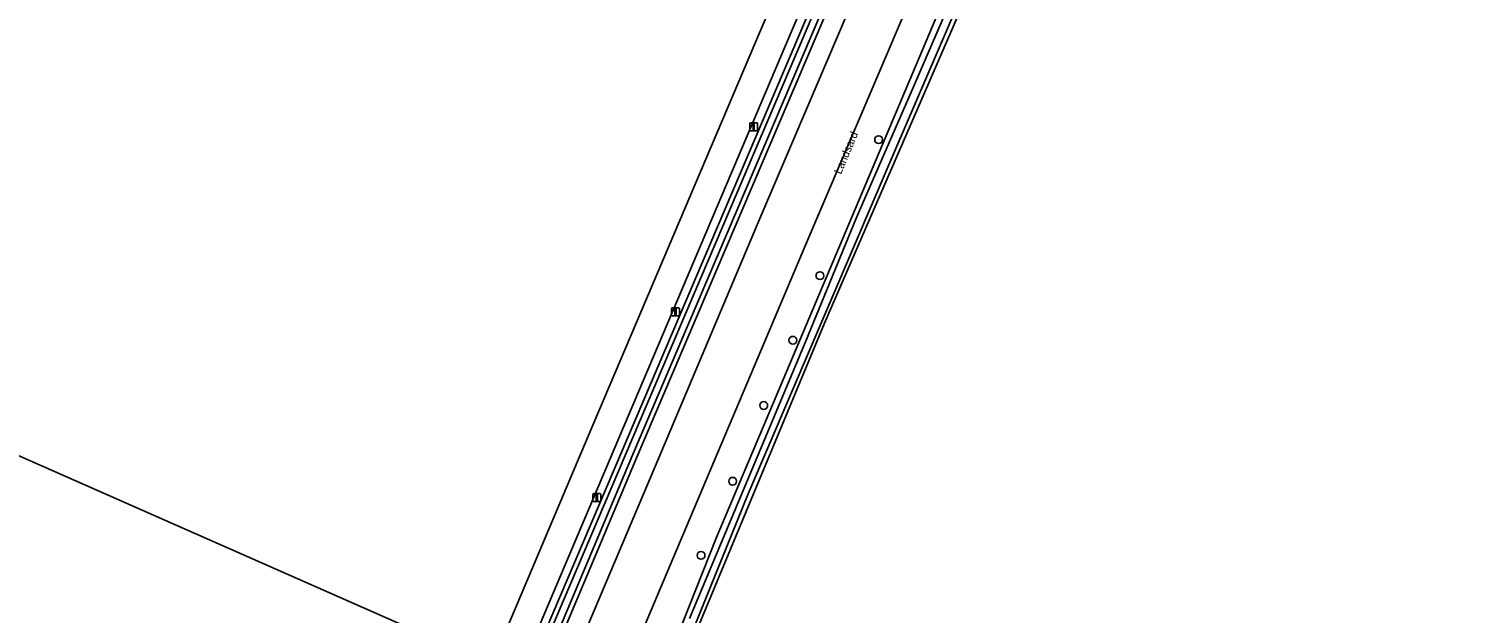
# Model space of a CAD drawing. Extents: x 155209 to 156748, y 385356 to 388487.
# Drawn here: x 155996.7 to 156175.3, y 386329.7 to 386402.7 of the extents above; entities that cross this region are included whole.
import ezdxf

# ---------------------------------------------------------------- set-up
doc = ezdxf.new("R2010")
doc.units = 0
for name, color, linetype in [('IMGEO_Boom', 7, 'Continuous'), ('IMGEO_Bouwland', 7, 'Continuous'), ('IMGEO_Fietspad_gesloten', 7, 'Continuous'), ('IMGEO_Gemengd_bos', 7, 'Continuous'), ('IMGEO_Groenvoorziening', 7, 'Continuous'), ('IMGEO_Lichtmast', 7, 'Continuous'), ('IMGEO_Oever', 7, 'Continuous'), ('IMGEO_Openbare_ruimte_label', 7, 'Continuous'), ('IMGEO_Rijbaan_lokaal_gesloten', 7, 'Continuous'), ('IMGEO_Waterloop', 7, 'Continuous')]:
    doc.layers.add(name, color=color, linetype=linetype)

msp = doc.modelspace()

# ---------------------------------------------------------------- linework, layer by layer
at = {"layer": 'IMGEO_Boom'}
for centre in [(156102.88, 386388.85), (156095.55, 386371.87), (156092.17, 386363.81), (156088.53, 386355.67), (156084.64, 386346.21), (156080.7, 386336.96)]:
    msp.add_circle(centre, 0.489, dxfattribs=at)
at = {"layer": 'IMGEO_Bouwland'}
msp.add_lwpolyline([(156111.26, 386456.76), (156125.52, 386490.13), (155948.54, 386558.13), (155923.76, 386500), (155881.05, 386399.78), (156052.24, 386324.4), (156054.54, 386323.39), (156054.72, 386323.81), (156066.59, 386351.85), (156087.98, 386402.17)], close=True, dxfattribs=at)
at = {"layer": 'IMGEO_Fietspad_gesloten'}
for points in [[(156139.32, 386522.4), (156125.52, 386490.13), (156111.26, 386456.76), (156087.98, 386402.17), (156066.59, 386351.85), (156054.72, 386323.81), (156054.54, 386323.39), (156042.98, 386296.08), (156023.43, 386249.93), (156022.29, 386247.24), (156019.64, 386240.99), (156006.63, 386210.28), (156004.07, 386204.24), (156001.82, 386199.14)], [(156005, 386197.04), (156010, 386208.82), (156023.01, 386239.56), (156046.41, 386294.89), (156058.06, 386322.41), (156069.84, 386350.23), (156091.23, 386400.62), (156114.61, 386455.4), (156142.59, 386521.01)]]:
    msp.add_lwpolyline(points, dxfattribs=at)
at = {"layer": 'IMGEO_Gemengd_bos'}
msp.add_lwpolyline([(156141.39, 386470.18), (156096.12, 386365.96), (156080.46, 386328.34), (156070.14, 386302.11), (156116.28, 386284.55), (156115.74, 386281.76), (156114.94, 386278.94), (156085.5, 386176.9)], dxfattribs=at)
msp.add_lwpolyline([(156052.24, 386324.4), (155881.05, 386399.78), (155850.31, 386327.79), (155900.27, 386304.88), (156000, 386260.38), (156021.46, 386250.81)], close=True, dxfattribs=at)
at = {"layer": 'IMGEO_Groenvoorziening'}
for points in [[(156007.59, 386189.1), (156009.57, 386193.77), (156010.6, 386196.2), (156010.67, 386196.17), (156028.11, 386237.4), (156051.19, 386291.96), (156074.96, 386348.06), (156088.15, 386379.28), (156100.53, 386408.28), (156128.81, 386474.42), (156158.86, 386544.7), (156160.63, 386548.86)], [(156063.56, 386292.58), (156064.47, 386293.87), (156065.2, 386295.28), (156082.6, 386339.09), (156140.39, 386475.84), (156151.1, 386500.48), (156159.62, 386521.29), (156166.27, 386536.26), (156169.74, 386543.04), (156171.1, 386545.31)], [(156164.88, 386542.11), (156134.86, 386471.86), (156106.55, 386405.65), (156094.2, 386376.75), (156080.93, 386345.4), (156057.35, 386289.66), (156034.16, 386234.85), (156023.57, 386209.85), (156023.39, 386207.82), (156024.11, 386207.89)], [(156026.29, 386245.49), (156070.68, 386349.65), (156144.95, 386523.89)], [(156146.86, 386523.08), (156072.67, 386349.22), (156028.61, 386244.59)], [(156142.59, 386521.01), (156114.61, 386455.4), (156091.23, 386400.62), (156069.84, 386350.23), (156058.06, 386322.41), (156046.41, 386294.89), (156023.01, 386239.56), (156010, 386208.82), (156005, 386197.04)]]:
    msp.add_lwpolyline(points, dxfattribs=at)
at = {"layer": 'IMGEO_Lichtmast'}
for p, q in [((156086.78, 386390.04), (156086.78, 386390.84)), ((156086.78, 386390.84), (156086.78, 386390.04)), ((156086.88, 386390.94), (156087.67, 386390.94)), ((156087.67, 386390.94), (156086.88, 386390.94)), ((156087.77, 386390.84), (156087.77, 386390.04)), ((156087.77, 386390.04), (156087.77, 386390.84)), ((156087.67, 386389.94), (156086.88, 386389.94)), ((156086.88, 386389.94), (156087.67, 386389.94)), ((156077, 386366.95), (156077, 386367.75)), ((156077, 386367.75), (156077, 386366.95)), ((156077.1, 386367.85), (156077.89, 386367.85)), ((156077.89, 386367.85), (156077.1, 386367.85)), ((156077.99, 386367.75), (156077.99, 386366.95)), ((156077.99, 386366.95), (156077.99, 386367.75)), ((156077.89, 386366.85), (156077.1, 386366.85)), ((156077.1, 386366.85), (156077.89, 386366.85)), ((156067.17, 386343.77), (156067.17, 386344.57)), ((156067.17, 386344.57), (156067.17, 386343.77)), ((156067.27, 386344.67), (156068.06, 386344.67)), ((156068.06, 386344.67), (156067.27, 386344.67)), ((156068.16, 386344.57), (156068.16, 386343.77)), ((156068.16, 386343.77), (156068.16, 386344.57)), ((156068.06, 386343.67), (156067.27, 386343.67)), ((156067.27, 386343.67), (156068.06, 386343.67))]:
    msp.add_line(p, q, dxfattribs=at)
for points in [[(156087.2, 386390.81), (156087.35, 386390.81), (156087.35, 386390.06), (156087.2, 386390.06), (156087.2, 386390.81)], [(156077.42, 386367.73), (156077.57, 386367.73), (156077.57, 386366.98), (156077.42, 386366.98), (156077.42, 386367.73)], [(156067.59, 386344.54), (156067.74, 386344.54), (156067.74, 386343.79), (156067.59, 386343.79), (156067.59, 386344.54)]]:
    msp.add_lwpolyline(points, dxfattribs=at)
for centre, start, end in [((156086.88, 386390.84), 90, 180), ((156086.88, 386390.84), 90, 180), ((156087.67, 386390.84), 0, 90), ((156087.67, 386390.84), 360, 90), ((156086.88, 386390.04), 180, 270), ((156086.88, 386390.04), 180, 270), ((156087.67, 386390.04), 270, 0), ((156087.67, 386390.04), 270, 0), ((156077.1, 386367.75), 90, 180), ((156077.1, 386367.75), 90, 180), ((156077.89, 386367.75), 0, 90), ((156077.89, 386367.75), 360, 90), ((156077.1, 386366.95), 180, 270), ((156077.1, 386366.95), 180, 270), ((156077.89, 386366.95), 270, 0), ((156077.89, 386366.95), 270, 0), ((156067.27, 386344.57), 90, 180), ((156067.27, 386344.57), 90, 180), ((156068.06, 386344.57), 0, 90), ((156068.06, 386344.57), 360, 90), ((156067.27, 386343.77), 180, 270), ((156067.27, 386343.77), 180, 270), ((156068.06, 386343.77), 270, 0), ((156068.06, 386343.77), 270, 0)]:
    msp.add_arc(centre, 0.1, start, end, dxfattribs=at)
at = {"layer": 'IMGEO_Oever'}
for points in [[(156123.57, 386433.22), (156141.4, 386475.41), (156152.11, 386500.05), (156160.63, 386520.86), (156167.26, 386535.78), (156170.7, 386542.51), (156172, 386544.66), (156173.01, 386545.83), (156173.54, 386546.4), (156175.33, 386547.03), (156173.2, 386547.64), (156172.2, 386546.57), (156171.1, 386545.31), (156169.74, 386543.04), (156166.27, 386536.26), (156159.62, 386521.29), (156151.1, 386500.48), (156140.39, 386475.84), (156082.6, 386339.09), (156065.2, 386295.28), (156064.47, 386293.87), (156063.56, 386292.58)], [(156144.95, 386523.89), (156070.68, 386349.65), (156026.29, 386245.49)], [(156026.79, 386245.14), (156071.23, 386349.41), (156145.41, 386523.44)], [(156146.22, 386523.1), (156072.12, 386349.46), (156027.95, 386244.58)], [(156028.61, 386244.59), (156072.67, 386349.22), (156146.86, 386523.08)], [(156067.31, 386295.14), (156067.82, 386296.21), (156068.73, 386298.52), (156070.14, 386302.11), (156080.46, 386328.34), (156096.12, 386365.96), (156141.39, 386470.18)], [(156079.27, 386329.07), (156093.76, 386363.6), (156100.11, 386379.14), (156107.37, 386395.72), (156123.57, 386433.22)], [(156117.96, 386417.73), (156104.89, 386387.44), (156086.6, 386344.66), (156074.44, 386314.65)]]:
    msp.add_lwpolyline(points, dxfattribs=at)
at = {"layer": 'IMGEO_Rijbaan_lokaal_gesloten'}
msp.add_lwpolyline([(156160.63, 386548.86), (156158.86, 386544.7), (156128.81, 386474.42), (156100.53, 386408.28), (156088.15, 386379.28), (156074.96, 386348.06), (156051.19, 386291.96), (156028.11, 386237.4), (156010.67, 386196.17), (156016.71, 386193.64), (156023.57, 386209.85), (156034.16, 386234.85), (156057.35, 386289.66), (156080.93, 386345.4), (156094.2, 386376.75), (156106.55, 386405.65)], dxfattribs=at)
at = {"layer": 'IMGEO_Waterloop'}
for points in [[(156145.41, 386523.44), (156071.23, 386349.41), (156026.79, 386245.14)], [(156027.95, 386244.58), (156072.12, 386349.46), (156146.22, 386523.1)], [(156123.57, 386433.22), (156107.37, 386395.72), (156100.11, 386379.14), (156093.76, 386363.6), (156079.27, 386329.07)], [(156074.44, 386314.65), (156086.6, 386344.66), (156104.89, 386387.44), (156117.96, 386417.73)]]:
    msp.add_lwpolyline(points, dxfattribs=at)

# ---------------------------------------------------------------- texts
at = {"layer": 'IMGEO_Openbare_ruimte_label'}
msp.add_text('Landsard', height=1, rotation=67.1552, dxfattribs=at).set_placement((156098.18, 386384.45))

doc.saveas('drawing.dxf')
